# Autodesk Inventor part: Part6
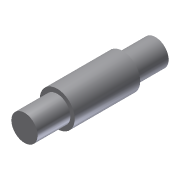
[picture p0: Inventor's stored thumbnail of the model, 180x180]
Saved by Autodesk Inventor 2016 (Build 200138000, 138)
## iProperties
Shininess: 77.0
Length Units: 11269
Angle Units: 11279
Time Units: 11290
Mass Units: 11283
Length Display Precision: 3
Angle Display Precision: 2
Created: 2002-01
Part Number: Part6
Document SubType Name: Modeling
Designer: ***
Density: 1 g/cm^3
Material: Generic
Appearance: Default
Density: 0.0
Volumn: 0.0
Area: 0.0
PropertySet Name: Model Information
Control State: 0
Master: False
Checked Out: False
Author: ***
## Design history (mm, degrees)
sketch "Sketch1"
  geometry: L1 (1.545, 32.521)-(-4.455, 32.521); L2 (-4.455, 32.521)-(-4.455, 17.521); L3 (-4.455, 17.521)-(-6.455, 17.521); L4 (-6.455, 17.521)-(-6.455, -12.479); L5 (-6.455, -12.479)-(-4.455, -12.479); L6 (-4.455, -12.479)-(-4.455, -27.479); L7 (-4.455, -27.479)-(1.545, -27.479); L8 (1.545, -27.479)-(1.545, 32.521)
  constraints: 16 end point, 5 parallel, 2 equal length, 1 collinear, 1 horizontal, 1 perpendicular
  dimensions: "d0" = 16 diameter of L4 L8; "d1" = 12 diameter of L2 L8; "d2" = 60 distance of L7.end L1.start; "d3" = 30 distance of L3.end L4.end
revolve "Revolution1" sketch "Sketch1" stored, may be unused: angle "d4" = 90 deg
body "Solid1"
